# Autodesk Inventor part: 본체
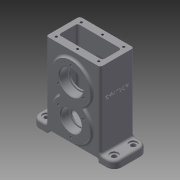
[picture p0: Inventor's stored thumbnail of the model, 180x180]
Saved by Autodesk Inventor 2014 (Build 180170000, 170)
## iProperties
Created: 2020-03
Part Number: 본체
Material: 알루미늄 6061
Document SubType Name: Modeling
Designer: mduedu
Density: 2.71 g/cm^3
Appearance: 기본값
Mass: 597.031 g
Surface Area: 576.062 cm^2
Volume: 220.307 cm^3
Author: mduedu
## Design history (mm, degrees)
sketch "스케치1"
  geometry: L1 (-56, 0)-(56, 0); L2 (56, 0)-(56, 10); L3 (-56, 10)-(-56, 0); L4 (37, 10)-(37, 114); L5 (37, 114)-(-37, 114); L6 (-37, 114)-(-37, 10); L7 (56, 10)-(37, 10); L8 (-37, 10)-(-56, 10); L9 (0, 0)-(0, 114); 1 further point
  constraints: 18 end point, 5 parallel, 2 midpoint, 2 vertical, 1 coincident, 1 horizontal, 1 perpendicular
  dimensions: "d0" = 112 distance of L1.start L1.end; "d2" = 10 distance of L1.end L2.end; "d3" = 114 distance between parallel lines of L5 L1; "d4" = 74 distance between parallel lines of L4 L6
extrude "돌출1" new body sketch "스케치1" stored distance "d5" = 46; taper "d6" = 0 deg
sketch "스케치2"
  geometry: L1 (56, 0)-(-56, 0) reference; C1 r 26 at (0, 34); C2 r 26 at (0, 79); 1 further point
  constraints: 2 centre point, 2 vertical alignment, 1 equal radius
  dimensions: "d7" = 52 diameter of C2; "d9" = 34 distance from line of C1.centre L1; "d10" = 45 distance of C2.centre C1.centre
extrude "돌출2" join sketch "스케치2" stored distance "d11" = 52; taper "d12" = 0 deg
fillet "모깎기1" dims "d13" = 3
fillet "모깎기2" dims "d14" = 3
fillet "모깎기3" dims "d15" = 10
fillet "모깎기4" dims "d16" = 3
fillet "모깎기5" dims "d17" = 3
sketch "스케치3"
  geometry: L1 (-30, 114)-(30, 114); L2 (30, 114)-(30, 13); L3 (30, 13)-(-30, 13); L4 (-30, 13)-(-30, 114); L5 (-34, 114)-(34, 114) reference; L6 (46, 0)-(-46, 0) reference; 2 further points
  constraints: 8 end point, 2 parallel, 1 collinear, 1 horizontal, 1 midpoint, 1 perpendicular, 1 vertical alignment
  dimensions: "d18" = 60 distance between parallel lines of L2 L4; "d20" = 13 distance between parallel lines of L3 L6
extrude "돌출3" cut sketch "스케치3" stored distance "d21" = 26; taper "d22" = 0 deg
fillet "모깎기6" dims "d23" = 3
fillet "모깎기7" dims "d24" = 3
sketch "스케치4"
  geometry: L1 (-35, 0)-(35, 0); L2 (35, 0)-(35, 5); L3 (35, 5)-(-35, 5); L4 (-35, 5)-(-35, 0); 2 further points
  constraints: 8 end point, 2 parallel, 1 coincident, 1 horizontal, 1 midpoint, 1 perpendicular
  dimensions: "d25" = 70 distance of L1.start L1.end; "d27" = 5 distance of L1.end L2.end
extrude "돌출4" cut sketch "스케치4" stored distance "d28" = 26; taper "d29" = 0 deg
fillet "모깎기8" dims "d30" = 3
sketch "스케치5"
  geometry: A1 r 10 centre (-86, 33) between (-86, 43) and (-96, 33) reference; A2 r 10 centre (-86, 7) between (-96, 7) and (-86, -3) reference; A3 r 10 centre (6, 7) between (6, -3) and (16, 7) reference; A4 r 10 centre (6, 33) between (16, 33) and (6, 43) reference; 5 further points
  constraints: 4 coincident
hole "구멍1" sketch "스케치5" at (-86, 33), (-86, 7), (6, 7), (6, 33) diameter "d31" = 6.6; stored, may be unused: countersink angle "d35" = 90 deg, drill point angle "d37" = 118 deg; dims "d32" = 6, "d33" = 11, "d34" = 2, "d36" = 8
sketch "스케치6"
  geometry: A1 r 26 centre (0, 34) between (-16.403, 54.172) and (16.403, 54.172) reference; A2 r 3 centre (18.296, 56.5) between (16.403, 58.828) and (16.403, 54.172) reference; A3 r 26 centre (0, 79) between (16.403, 58.828) and (-16.403, 58.828) reference; A4 r 3 centre (-18.296, 56.5) between (-16.403, 54.172) and (-16.403, 58.828) reference; 2 further points
  constraints: 1 coincident
hole "구멍2" sketch "스케치6" at (0, 79) diameter "d38" = 28; stored, may be unused: countersink angle "d42" = 90 deg, drill point angle "d44" = 118 deg; dims "d39" = 6, "d40" = 32, "d41" = 11, "d43" = 8
sketch "스케치7"
  geometry: C1 r 16 at (0, 79) reference; A1 r 26 centre (0, 34) between (-16.403, 54.172) and (16.403, 54.172) reference; A2 r 3 centre (18.296, 56.5) between (16.403, 58.828) and (16.403, 54.172) reference; A3 r 26 centre (0, 79) between (16.403, 58.828) and (-16.403, 58.828) reference; A4 r 3 centre (-18.296, 56.5) between (-16.403, 54.172) and (-16.403, 58.828) reference; 2 further points
  constraints: 1 coincident
hole "구멍3" sketch "스케치7" at (0, 34) diameter "d45" = 24; stored, may be unused: countersink angle "d49" = 90 deg, drill point angle "d51" = 118 deg; dims "d46" = 6, "d47" = 28, "d48" = 11, "d50" = 8
sketch "스케치8"
  geometry: C1 r 14 at (0, 34) reference; A1 r 26 centre (0, 34) between (-16.403, 54.172) and (16.403, 54.172) reference; A2 r 3 centre (18.296, 56.5) between (16.403, 58.828) and (16.403, 54.172) reference; A3 r 26 centre (0, 79) between (16.403, 58.828) and (-16.403, 58.828) reference; A4 r 3 centre (-18.296, 56.5) between (-16.403, 54.172) and (-16.403, 58.828) reference; 2 further points
  constraints: 1 coincident
hole "구멍4" sketch "스케치8" at (0, 79) diameter "d52" = 24; stored, may be unused: countersink angle "d56" = 90 deg, drill point angle "d58" = 118 deg; dims "d53" = 6, "d54" = 28, "d55" = 11, "d57" = 8
sketch "스케치9" dims "d59" = 40
  geometry: C1 r 14 at (0, 34) reference; C2 r 16 at (0, 79) reference; A1 r 26 centre (0, 34) between (-16.403, 54.172) and (16.403, 54.172) reference; A2 r 3 centre (18.296, 56.5) between (16.403, 58.828) and (16.403, 54.172) reference; A3 r 26 centre (0, 79) between (16.403, 58.828) and (-16.403, 58.828) reference; A4 r 3 centre (-18.296, 56.5) between (-16.403, 54.172) and (-16.403, 58.828) reference; 3 further points
  constraints: 2 vertical alignment, 1 coincident, 2 other
hole "구멍5" sketch "스케치9" at (0, 99) diameter "d61" = 3.242; stored, may be unused: countersink angle "d65" = 90 deg, drill point angle "d67" = 118 deg; dims "d62" = 8, "d63" = 28, "d64" = 11, "d66" = 10
sketch "스케치10" dims "d71" = 40
  geometry: C1 r 1.621 at (17.321, 69) reference; C2 r 1.621 at (-17.321, 69) reference; C3 r 1.621 at (0, 99) reference; C4 r 14 at (0, 34) reference; C5 r 16 at (0, 79) reference; A1 r 26 centre (0, 34) between (-16.403, 54.172) and (16.403, 54.172) reference; A2 r 3 centre (18.296, 56.5) between (16.403, 58.828) and (16.403, 54.172) reference; A3 r 26 centre (0, 79) between (16.403, 58.828) and (-16.403, 58.828) reference; A4 r 3 centre (-18.296, 56.5) between (-16.403, 54.172) and (-16.403, 58.828) reference; 3 further points
  constraints: 2 vertical alignment, 1 coincident, 2 other
hole "구멍6" sketch "스케치10" at (0, 14) diameter "d72" = 3.242; stored, may be unused: countersink angle "d76" = 90 deg, drill point angle "d78" = 118 deg; dims "d73" = 8, "d74" = 28, "d75" = 11, "d77" = 10
sketch "스케치11"
  geometry: L1 (5, 6)-(63, 6); L2 (63, 6)-(63, 40); L3 (63, 40)-(5, 40); L4 (5, 40)-(5, 6); L5 (5, 6)-(63, 40); L6 (63, 6)-(5, 40); 7 further points
  constraints: 12 end point, 4 coincident, 4 midpoint, 2 parallel, 1 horizontal, 1 perpendicular
  dimensions: "d82" = 58 distance of L3.end L2.end; "d83" = 34 distance of L2.end L1.end
hole "구멍7" sketch "스케치11" at (5, 40), (63, 40), (63, 6), (5, 6), (34, 6), (34, 40) diameter "d84" = 3.242; stored, may be unused: countersink angle "d88" = 90 deg, drill point angle "d90" = 118 deg; dims "d85" = 8, "d86" = 28, "d87" = 11, "d89" = 10
fillet "모깎기9" dims "d91" = 0.3
chamfer "모따기1" distance "d92" = 1; stored, may be unused: second distance "d93" = 2, angle "d94" = 45 deg
sketch "스케치12"
  geometry: 2 further points
  constraints: 1 coincident
hole "구멍8" sketch "스케치12" at (0, -23) diameter "d95" = 4.917; stored, may be unused: countersink angle "d99" = 90 deg, drill point angle "d101" = 118 deg; dims "d96" = 8, "d97" = 12, "d98" = 1, "d100" = 10
sketch "스케치13"
  geometry: L1 (33, -13)-(7, -13) reference; L2 (40, 101)-(0, 101) reference; 3 further points
  constraints: 1 midpoint, 1 vertical alignment, 1 other
  dimensions: "d102" = 40 distance from line of point (20, 61) L2
feature "엠보싱1" sketch "스케치13" dims "d0" = 112, "d2" = 10, "d3" = 114, "d4" = 74, "d13" = 3, "d103" = 0.5, "d104" = 0
node "솔리드1"
mirror "대칭1"
pattern_circular "원형 패턴1" dims angle "d69" = 360 deg
pattern_circular "원형 패턴2" dims angle "d80" = 360 deg
mirror "대칭2"
node "투영된 루프1"
node "투영된 루프2"
node "투영된 루프3"
node "투영된 루프4"
node "투영된 루프5"
